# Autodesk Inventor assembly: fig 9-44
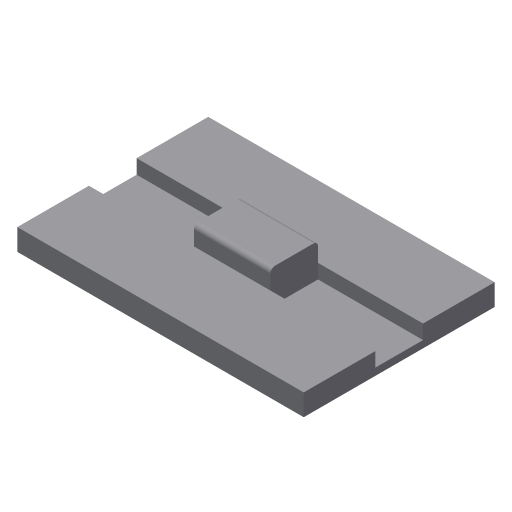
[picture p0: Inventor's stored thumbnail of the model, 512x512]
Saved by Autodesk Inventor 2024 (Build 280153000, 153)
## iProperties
Created: 2013-07
Part Number: fig 9-44
Document SubType Name: Assembly
Designer: CADCIM
Author: CADCIM
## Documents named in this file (3)
- D:\PROJECTS\Project 2023\RESOURCES INVENTOR 2024\RESOURCES INVENTOR 2024\Inventor_2023_Part\Inventor_2024_Part\c09_Inv_2024_prt\fig 9-45.iam
- D:\PROJECTS\Project 2023\RESOURCES INVENTOR 2024\RESOURCES INVENTOR 2024\Inventor_2023_Part\Inventor_2024_Part\c09_Inv_2024_prt\15.ipt
- D:\PROJECTS\Project 2023\RESOURCES INVENTOR 2024\RESOURCES INVENTOR 2024\Inventor_2023_Part\Inventor_2024_Part\c09_Inv_2024_prt\16.ipt
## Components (2 placed, 2 different names)
1. 15:1 — Slider:1
2. 16:1 — Slider:1
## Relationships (1: TranslationJoint 1)
- Slider:1 [TranslationJoint]: 15:1 ↔ 16:1
